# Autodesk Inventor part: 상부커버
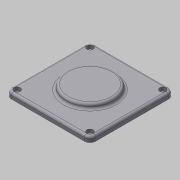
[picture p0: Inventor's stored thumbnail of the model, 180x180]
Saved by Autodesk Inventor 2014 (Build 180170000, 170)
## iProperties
Created: 2018-09
Part Number: 상부커버
Document SubType Name: Modeling
Density: 2.71 g/cm^3
Material: 알루미늄 6061
Mass: 249.405 g
Surface Area: 254.001 cm^2
Volume: 92.0315 cm^3
Appearance: 알루미늄 - 평지
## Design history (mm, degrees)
sketch "스케치5"
  geometry: L1 (-52.5, -52.5)-(52.5, -52.5); L2 (52.5, -52.5)-(52.5, 52.5); L3 (52.5, 52.5)-(-52.5, 52.5); L4 (-52.5, 52.5)-(-52.5, -52.5); L5 (-52.5, -52.5)-(52.5, 52.5); L6 (52.5, -52.5)-(-52.5, 52.5); 1 further point
  constraints: 12 end point, 2 midpoint, 2 parallel, 1 horizontal, 1 perpendicular
  dimensions: "d35" = 105 distance of L3.end L2.end; "d36" = 105 distance of L2.end L1.end
extrude "돌출4" new body sketch "스케치5" distance "d37" = 7; taper "d38" = 0 deg
fillet "모깎기4" dims "d39" = 7
sketch "스케치2"
  geometry: C1 r 30 at (0, 0); 2 further points
  constraints: 2 coincident, 1 centre point
  dimensions: "d4" = 60 diameter of C1
extrude "돌출3" join sketch "스케치2" distance "d5" = 6; taper "d6" = 0 deg
fillet "모깎기1" dims "d7" = 3
sketch "스케치4"
  geometry: L1 (52.5, -45.5)-(52.5, 45.5) reference; L2 (-45.5, -52.5)-(45.5, -52.5) reference; L3 (-52.5, 45.5)-(-52.5, -45.5) reference; L4 (45.5, 52.5)-(-45.5, 52.5) reference; A1 r 7 centre (45.5, 45.5) between (52.5, 45.5) and (45.5, 52.5) reference; A2 r 7 centre (45.5, -45.5) between (45.5, -52.5) and (52.5, -45.5) reference; A3 r 7 centre (-45.5, -45.5) between (-52.5, -45.5) and (-45.5, -52.5) reference; A4 r 7 centre (-45.5, 45.5) between (-45.5, 52.5) and (-52.5, 45.5) reference; 4 further points
  constraints: 4 coincident
hole "구멍3" sketch "스케치4" at (-45.5, 45.5), (-45.5, -45.5), (45.5, -45.5), (45.5, 45.5) diameter "d43" = 4.5; stored, may be unused: countersink angle "d47" = 90 deg, drill point angle "d49" = 118 deg; dims "d44" = 6, "d45" = 8, "d46" = 4.4, "d48" = 8
fillet "모깎기3" dims "d19" = 3
node "솔리드1"
node "솔리드2"
node "투영된 루프2"
